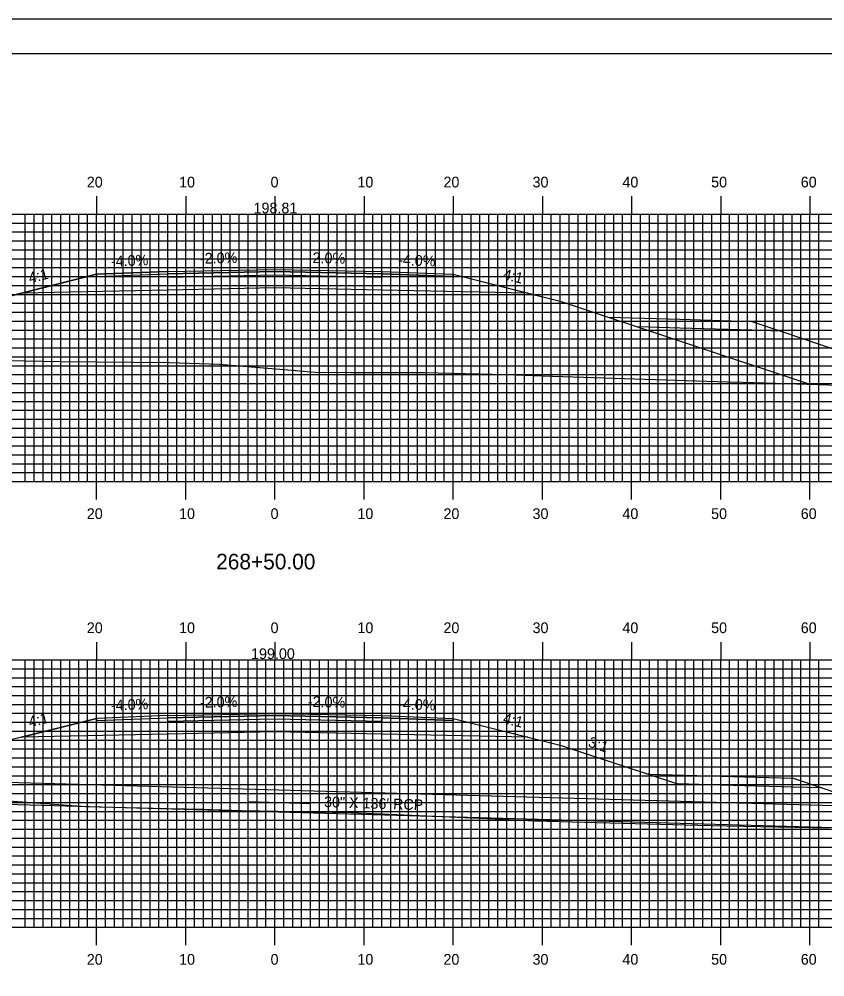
# Model space of a CAD drawing. Extents: x 1807832 to 1808175, y 442591 to 442811.
# Drawn here: x 1807969.1 to 1808059.5, y 442703.1 to 442810.5 of the extents above; entities that cross this region are included whole.
import ezdxf

# ---------------------------------------------------------------- set-up
doc = ezdxf.new("R2010")
doc.units = 0
for name, color, linetype in [('ANNOTATION', 7, 'Continuous'), ('BORDER', 7, 'Continuous'), ('D_Drainage_Culvert', 7, 'Continuous'), ('D_Drainage_Text', 7, 'Continuous'), ('D_Roadway_Centerline', 7, 'Continuous'), ('D_Roadway_Centerline_Text', 7, 'Continuous'), ('D_Roadway_Drive_Gravel', 7, 'Continuous'), ('D_Roadway_Edge_Shoulder', 7, 'Continuous'), ('D_Roadway_Edge_TW', 7, 'Continuous'), ('D_Roadway_FinishedGrade', 7, 'Continuous'), ('D_Roadway_Pavement', 7, 'Continuous'), ('D_Roadway_SlopeLines', 7, 'Continuous'), ('D_Roadway_SubGrade', 7, 'Continuous'), ('H_V ANNOTATION', 7, 'Continuous'), ('MAJOR', 7, 'Continuous'), ('MINOR', 7, 'Continuous'), ('PLOT BOUNDARY', 7, 'Continuous'), ('S_Roadway_Centerline', 7, 'Continuous')]:
    doc.layers.add(name, color=color, linetype=linetype)

msp = doc.modelspace()

# ---------------------------------------------------------------- linework, layer by layer
at = {"layer": 'BORDER'}
msp.add_lwpolyline([(1807848.18, 442596.67), (1808168.18, 442596.67), (1808168.18, 442806.67), (1807848.18, 442806.67)], close=True, dxfattribs=at)
at = {"layer": 'D_Drainage_Culvert'}
for p, q in [((1808039.7, 442725.85), (1808039.65, 442725.85)), ((1808042.97, 442724.76), (1808042.95, 442724.76)), ((1807994.78, 442722.79), (1808001.78, 442722.56))]:
    msp.add_line(p, q, dxfattribs=at)
msp.add_lwpolyline([(1807935.84, 442723.35), (1807935.9, 442725.84), (1808072.45, 442721.98), (1808072.39, 442719.49)], close=True, dxfattribs=at)
at = {"layer": 'D_Roadway_Centerline'}
msp.add_lwpolyline([(1807947.22, 442772.73), (1807965.78, 442778.92), (1807969.42, 442779.82), (1807977.78, 442781.92), (1807985.78, 442782.24), (1807997.78, 442782.48), (1808009.78, 442782.24), (1808017.78, 442781.92), (1808026.15, 442779.82), (1808029.78, 442778.92), (1808057.78, 442769.58)], dxfattribs=at)
at = {"layer": 'D_Roadway_Drive_Gravel'}
for points in [[(1808035.19, 442777.11), (1808043.19, 442776.88), (1808051.29, 442776.64), (1808054.53, 442775.55), (1808051.29, 442775.64), (1808043.19, 442775.88), (1808038.48, 442776.02)], [(1808039.7, 442725.84), (1808039.7, 442725.85), (1808047.8, 442725.62), (1808055.9, 442725.4), (1808059.14, 442724.31), (1808055.91, 442724.4), (1808047.81, 442724.62), (1808042.97, 442724.76)]]:
    msp.add_lwpolyline(points, dxfattribs=at)
at = {"layer": 'D_Roadway_Edge_Shoulder'}
for points in [[(1807985.78, 442782.24), (1807977.78, 442781.92), (1807977.78, 442781.67), (1807985.78, 442781.99)], [(1808009.78, 442782.24), (1808017.78, 442781.92), (1808017.78, 442781.67), (1808009.78, 442781.99)], [(1807985.78, 442732.42), (1807977.78, 442732.1), (1807977.78, 442731.85), (1807985.78, 442732.17)], [(1808009.78, 442732.42), (1808017.78, 442732.1), (1808017.78, 442731.85), (1808009.78, 442732.17)]]:
    msp.add_lwpolyline(points, close=True, dxfattribs=at)
at = {"layer": 'D_Roadway_Edge_TW'}
for points in [[(1807985.78, 442781.99), (1807985.78, 442782.24), (1807997.78, 442782.48), (1808009.78, 442782.24), (1808009.78, 442781.99), (1807997.78, 442782.23)], [(1807985.78, 442732.17), (1807985.78, 442732.42), (1807997.78, 442732.66), (1808009.78, 442732.42), (1808009.78, 442732.17), (1807997.78, 442732.41)]]:
    msp.add_lwpolyline(points, close=True, dxfattribs=at)
at = {"layer": 'D_Roadway_FinishedGrade'}
for p, q in [((1807977.78, 442732.1), (1807965.78, 442729.1)), ((1808054.15, 442719.94), (1808056.15, 442719.94))]:
    msp.add_line(p, q, dxfattribs=at)
at = {"layer": 'D_Roadway_Pavement'}
for points in [[(1807985.78, 442781.57), (1807985.78, 442781.99), (1807997.78, 442782.23), (1808009.78, 442781.99), (1808009.78, 442781.57), (1807997.78, 442781.81)], [(1807985.78, 442731.76), (1807985.78, 442732.17), (1807997.78, 442732.41), (1808009.78, 442732.17), (1808009.78, 442731.76), (1807997.78, 442732)]]:
    msp.add_lwpolyline(points, close=True, dxfattribs=at)
at = {"layer": 'D_Roadway_SlopeLines'}
for points in [[(1807977.78, 442781.92), (1807965.78, 442778.92), (1807947.22, 442772.73)], [(1808017.78, 442781.92), (1808029.78, 442778.92), (1808057.78, 442769.58)], [(1808051.29, 442776.64), (1808054.53, 442775.55), (1808073.28, 442769.2)], [(1808017.78, 442732.1), (1808029.78, 442729.1), (1808042.95, 442724.76)], [(1808055.9, 442725.4), (1808059.14, 442724.31), (1808062.76, 442723.09)]]:
    msp.add_lwpolyline(points, dxfattribs=at)
at = {"layer": 'D_Roadway_SubGrade'}
for points in [[(1807985.78, 442780.15), (1807969.42, 442779.82), (1807977.78, 442781.92), (1807977.78, 442781.67), (1807985.78, 442781.99), (1807997.78, 442782.23), (1808009.78, 442781.99), (1808017.78, 442781.67), (1808017.78, 442781.92), (1808026.15, 442779.82), (1808009.78, 442780.15), (1807997.78, 442780.39)], [(1807985.78, 442730.34), (1807969.42, 442730.01), (1807977.78, 442732.1), (1807977.78, 442731.85), (1807985.78, 442732.17), (1807997.78, 442732.41), (1808009.78, 442732.17), (1808017.78, 442731.85), (1808017.78, 442732.1), (1808026.15, 442730.01), (1808009.78, 442730.34), (1807997.78, 442730.58)]]:
    msp.add_lwpolyline(points, close=True, dxfattribs=at)
at = {"layer": 'MAJOR'}
for p, q in [((1807977.78, 442790.67), (1807977.78, 442788.67)), ((1807987.78, 442790.67), (1807987.78, 442788.67)), ((1807997.78, 442790.67), (1807997.78, 442788.67)), ((1808007.78, 442790.67), (1808007.78, 442788.67)), ((1808017.78, 442790.67), (1808017.78, 442788.67)), ((1808027.78, 442790.67), (1808027.78, 442788.67)), ((1808037.78, 442790.67), (1808037.78, 442788.67)), ((1808047.78, 442790.67), (1808047.78, 442788.67)), ((1808057.78, 442790.67), (1808057.78, 442788.67)), ((1807857.78, 442788.67), (1808137.78, 442788.67)), ((1807857.78, 442788.67), (1808137.78, 442788.67)), ((1807977.78, 442758.67), (1807977.78, 442788.67)), ((1807987.78, 442758.67), (1807987.78, 442788.67)), ((1807997.78, 442758.67), (1807997.78, 442788.67)), ((1808007.78, 442758.67), (1808007.78, 442788.67)), ((1808017.78, 442758.67), (1808017.78, 442788.67)), ((1808027.78, 442758.67), (1808027.78, 442788.67)), ((1808037.78, 442758.67), (1808037.78, 442788.67)), ((1808047.78, 442758.67), (1808047.78, 442788.67)), ((1808057.78, 442758.67), (1808057.78, 442788.67)), ((1807857.78, 442783.67), (1808137.78, 442783.67)), ((1807857.78, 442778.67), (1808137.78, 442778.67)), ((1807857.78, 442773.67), (1808137.78, 442773.67)), ((1807857.78, 442768.67), (1808137.78, 442768.67)), ((1807857.78, 442763.67), (1808137.78, 442763.67)), ((1807857.78, 442758.67), (1808137.78, 442758.67)), ((1807857.78, 442758.67), (1808137.78, 442758.67)), ((1807977.78, 442756.66), (1807977.78, 442758.67)), ((1807987.78, 442756.66), (1807987.78, 442758.67)), ((1807997.78, 442756.66), (1807997.78, 442758.67)), ((1808007.78, 442756.66), (1808007.78, 442758.67)), ((1808017.78, 442756.66), (1808017.78, 442758.67)), ((1808027.78, 442756.66), (1808027.78, 442758.67)), ((1808037.78, 442756.66), (1808037.78, 442758.67)), ((1808047.78, 442756.66), (1808047.78, 442758.67)), ((1808057.78, 442756.66), (1808057.78, 442758.67)), ((1807977.78, 442740.67), (1807977.78, 442738.67)), ((1807987.78, 442740.67), (1807987.78, 442738.67)), ((1807997.78, 442740.67), (1807997.78, 442738.67)), ((1808007.78, 442740.67), (1808007.78, 442738.67)), ((1808017.78, 442740.67), (1808017.78, 442738.67)), ((1808027.78, 442740.67), (1808027.78, 442738.67)), ((1808037.78, 442740.67), (1808037.78, 442738.67)), ((1808047.78, 442740.67), (1808047.78, 442738.67)), ((1808057.78, 442740.67), (1808057.78, 442738.67)), ((1807857.78, 442738.67), (1808137.78, 442738.67)), ((1807857.78, 442738.67), (1808137.78, 442738.67)), ((1807977.78, 442708.67), (1807977.78, 442738.67)), ((1807987.78, 442708.67), (1807987.78, 442738.67)), ((1807997.78, 442708.67), (1807997.78, 442738.67)), ((1808007.78, 442708.67), (1808007.78, 442738.67)), ((1808017.78, 442708.67), (1808017.78, 442738.67)), ((1808027.78, 442708.67), (1808027.78, 442738.67)), ((1808037.78, 442708.67), (1808037.78, 442738.67)), ((1808047.78, 442708.67), (1808047.78, 442738.67)), ((1808057.78, 442708.67), (1808057.78, 442738.67)), ((1807857.78, 442733.67), (1808137.78, 442733.67)), ((1807857.78, 442728.67), (1808137.78, 442728.67)), ((1807857.78, 442723.67), (1808137.78, 442723.67)), ((1807857.78, 442718.67), (1808137.78, 442718.67)), ((1807857.78, 442713.67), (1808137.78, 442713.67)), ((1807857.78, 442708.67), (1808137.78, 442708.67)), ((1807857.78, 442708.67), (1808137.78, 442708.67)), ((1807977.78, 442706.66), (1807977.78, 442708.67)), ((1807987.78, 442706.66), (1807987.78, 442708.67)), ((1807997.78, 442706.66), (1807997.78, 442708.67)), ((1808007.78, 442706.66), (1808007.78, 442708.67)), ((1808017.78, 442706.66), (1808017.78, 442708.67)), ((1808027.78, 442706.66), (1808027.78, 442708.67)), ((1808037.78, 442706.66), (1808037.78, 442708.67)), ((1808047.78, 442706.66), (1808047.78, 442708.67)), ((1808057.78, 442706.66), (1808057.78, 442708.67))]:
    msp.add_line(p, q, dxfattribs=at)
at = {"layer": 'MINOR'}
for p, q in [((1807969.78, 442758.67), (1807969.78, 442788.67)), ((1807970.78, 442758.67), (1807970.78, 442788.67)), ((1807971.78, 442758.67), (1807971.78, 442788.67)), ((1807972.78, 442758.67), (1807972.78, 442788.67)), ((1807973.78, 442758.67), (1807973.78, 442788.67)), ((1807974.78, 442758.67), (1807974.78, 442788.67)), ((1807975.78, 442758.67), (1807975.78, 442788.67)), ((1807976.78, 442758.67), (1807976.78, 442788.67)), ((1807978.78, 442758.67), (1807978.78, 442788.67)), ((1807979.78, 442758.67), (1807979.78, 442788.67)), ((1807980.78, 442758.67), (1807980.78, 442788.67)), ((1807981.78, 442758.67), (1807981.78, 442788.67)), ((1807982.78, 442758.67), (1807982.78, 442788.67)), ((1807983.78, 442758.67), (1807983.78, 442788.67)), ((1807984.78, 442758.67), (1807984.78, 442788.67)), ((1807985.78, 442758.67), (1807985.78, 442788.67)), ((1807986.78, 442758.67), (1807986.78, 442788.67)), ((1807988.78, 442758.67), (1807988.78, 442788.67)), ((1807989.78, 442758.67), (1807989.78, 442788.67)), ((1807990.78, 442758.67), (1807990.78, 442788.67)), ((1807991.78, 442758.67), (1807991.78, 442788.67)), ((1807992.78, 442758.67), (1807992.78, 442788.67)), ((1807993.78, 442758.67), (1807993.78, 442788.67)), ((1807994.78, 442758.67), (1807994.78, 442788.67)), ((1807995.78, 442758.67), (1807995.78, 442788.67)), ((1807996.78, 442758.67), (1807996.78, 442788.67)), ((1807998.78, 442758.67), (1807998.78, 442788.67)), ((1807999.78, 442758.67), (1807999.78, 442788.67)), ((1808000.78, 442758.67), (1808000.78, 442788.67)), ((1808001.78, 442758.67), (1808001.78, 442788.67)), ((1808002.78, 442758.67), (1808002.78, 442788.67)), ((1808003.78, 442758.67), (1808003.78, 442788.67)), ((1808004.78, 442758.67), (1808004.78, 442788.67)), ((1808005.78, 442758.67), (1808005.78, 442788.67)), ((1808006.78, 442758.67), (1808006.78, 442788.67)), ((1808008.78, 442758.67), (1808008.78, 442788.67)), ((1808009.78, 442758.67), (1808009.78, 442788.67)), ((1808010.78, 442758.67), (1808010.78, 442788.67)), ((1808011.78, 442758.67), (1808011.78, 442788.67)), ((1808012.78, 442758.67), (1808012.78, 442788.67)), ((1808013.78, 442758.67), (1808013.78, 442788.67)), ((1808014.78, 442758.67), (1808014.78, 442788.67)), ((1808015.78, 442758.67), (1808015.78, 442788.67)), ((1808016.78, 442758.67), (1808016.78, 442788.67)), ((1808018.78, 442758.67), (1808018.78, 442788.67)), ((1808019.78, 442758.67), (1808019.78, 442788.67)), ((1808020.78, 442758.67), (1808020.78, 442788.67)), ((1808021.78, 442758.67), (1808021.78, 442788.67)), ((1808022.78, 442758.67), (1808022.78, 442788.67)), ((1808023.78, 442758.67), (1808023.78, 442788.67)), ((1808024.78, 442758.67), (1808024.78, 442788.67)), ((1808025.78, 442758.67), (1808025.78, 442788.67)), ((1808026.78, 442758.67), (1808026.78, 442788.67)), ((1808028.78, 442758.67), (1808028.78, 442788.67)), ((1808029.78, 442758.67), (1808029.78, 442788.67)), ((1808030.78, 442758.67), (1808030.78, 442788.67)), ((1808031.78, 442758.67), (1808031.78, 442788.67)), ((1808032.78, 442758.67), (1808032.78, 442788.67)), ((1808033.78, 442758.67), (1808033.78, 442788.67)), ((1808034.78, 442758.67), (1808034.78, 442788.67)), ((1808035.78, 442758.67), (1808035.78, 442788.67)), ((1808036.78, 442758.67), (1808036.78, 442788.67)), ((1808038.78, 442758.67), (1808038.78, 442788.67)), ((1808039.78, 442758.67), (1808039.78, 442788.67)), ((1808040.78, 442758.67), (1808040.78, 442788.67)), ((1808041.78, 442758.67), (1808041.78, 442788.67)), ((1808042.78, 442758.67), (1808042.78, 442788.67)), ((1808043.78, 442758.67), (1808043.78, 442788.67)), ((1808044.78, 442758.67), (1808044.78, 442788.67)), ((1808045.78, 442758.67), (1808045.78, 442788.67)), ((1808046.78, 442758.67), (1808046.78, 442788.67)), ((1808048.78, 442758.67), (1808048.78, 442788.67)), ((1808049.78, 442758.67), (1808049.78, 442788.67)), ((1808050.78, 442758.67), (1808050.78, 442788.67)), ((1808051.78, 442758.67), (1808051.78, 442788.67)), ((1808052.78, 442758.67), (1808052.78, 442788.67)), ((1808053.78, 442758.67), (1808053.78, 442788.67)), ((1808054.78, 442758.67), (1808054.78, 442788.67)), ((1808055.78, 442758.67), (1808055.78, 442788.67)), ((1808056.78, 442758.67), (1808056.78, 442788.67)), ((1808058.78, 442758.67), (1808058.78, 442788.67)), ((1807857.78, 442787.67), (1808137.78, 442787.67)), ((1807857.78, 442786.67), (1808137.78, 442786.67)), ((1807857.78, 442785.67), (1808137.78, 442785.67)), ((1807857.78, 442784.67), (1808137.78, 442784.67)), ((1807857.78, 442782.67), (1808137.78, 442782.67)), ((1807857.78, 442781.67), (1808137.78, 442781.67)), ((1807857.78, 442780.67), (1808137.78, 442780.67)), ((1807857.78, 442779.67), (1808137.78, 442779.67)), ((1807857.78, 442777.67), (1808137.78, 442777.67)), ((1807857.78, 442776.67), (1808137.78, 442776.67)), ((1807857.78, 442775.67), (1808137.78, 442775.67)), ((1807857.78, 442774.67), (1808137.78, 442774.67)), ((1807857.78, 442772.67), (1808137.78, 442772.67)), ((1807857.78, 442771.67), (1808137.78, 442771.67)), ((1807857.78, 442770.67), (1808137.78, 442770.67)), ((1807857.78, 442769.67), (1808137.78, 442769.67)), ((1807857.78, 442767.67), (1808137.78, 442767.67)), ((1807857.78, 442766.67), (1808137.78, 442766.67)), ((1807857.78, 442765.67), (1808137.78, 442765.67)), ((1807857.78, 442764.67), (1808137.78, 442764.67)), ((1807857.78, 442762.67), (1808137.78, 442762.67)), ((1807857.78, 442761.67), (1808137.78, 442761.67)), ((1807857.78, 442760.67), (1808137.78, 442760.67)), ((1807857.78, 442759.67), (1808137.78, 442759.67)), ((1807969.78, 442708.67), (1807969.78, 442738.67)), ((1807970.78, 442708.67), (1807970.78, 442738.67)), ((1807971.78, 442708.67), (1807971.78, 442738.67)), ((1807972.78, 442708.67), (1807972.78, 442738.67)), ((1807973.78, 442708.67), (1807973.78, 442738.67)), ((1807974.78, 442708.67), (1807974.78, 442738.67)), ((1807975.78, 442708.67), (1807975.78, 442738.67)), ((1807976.78, 442708.67), (1807976.78, 442738.67)), ((1807978.78, 442708.67), (1807978.78, 442738.67)), ((1807979.78, 442708.67), (1807979.78, 442738.67)), ((1807980.78, 442708.67), (1807980.78, 442738.67)), ((1807981.78, 442708.67), (1807981.78, 442738.67)), ((1807982.78, 442708.67), (1807982.78, 442738.67)), ((1807983.78, 442708.67), (1807983.78, 442738.67)), ((1807984.78, 442708.67), (1807984.78, 442738.67)), ((1807985.78, 442708.67), (1807985.78, 442738.67)), ((1807986.78, 442708.67), (1807986.78, 442738.67)), ((1807988.78, 442708.67), (1807988.78, 442738.67)), ((1807989.78, 442708.67), (1807989.78, 442738.67)), ((1807990.78, 442708.67), (1807990.78, 442738.67)), ((1807991.78, 442708.67), (1807991.78, 442738.67)), ((1807992.78, 442708.67), (1807992.78, 442738.67)), ((1807993.78, 442708.67), (1807993.78, 442738.67)), ((1807994.78, 442708.67), (1807994.78, 442738.67)), ((1807995.78, 442708.67), (1807995.78, 442738.67)), ((1807996.78, 442708.67), (1807996.78, 442738.67)), ((1807998.78, 442708.67), (1807998.78, 442738.67)), ((1807999.78, 442708.67), (1807999.78, 442738.67)), ((1808000.78, 442708.67), (1808000.78, 442738.67)), ((1808001.78, 442708.67), (1808001.78, 442738.67)), ((1808002.78, 442708.67), (1808002.78, 442738.67)), ((1808003.78, 442708.67), (1808003.78, 442738.67)), ((1808004.78, 442708.67), (1808004.78, 442738.67)), ((1808005.78, 442708.67), (1808005.78, 442738.67)), ((1808006.78, 442708.67), (1808006.78, 442738.67)), ((1808008.78, 442708.67), (1808008.78, 442738.67)), ((1808009.78, 442708.67), (1808009.78, 442738.67)), ((1808010.78, 442708.67), (1808010.78, 442738.67)), ((1808011.78, 442708.67), (1808011.78, 442738.67)), ((1808012.78, 442708.67), (1808012.78, 442738.67)), ((1808013.78, 442708.67), (1808013.78, 442738.67)), ((1808014.78, 442708.67), (1808014.78, 442738.67)), ((1808015.78, 442708.67), (1808015.78, 442738.67)), ((1808016.78, 442708.67), (1808016.78, 442738.67)), ((1808018.78, 442708.67), (1808018.78, 442738.67)), ((1808019.78, 442708.67), (1808019.78, 442738.67)), ((1808020.78, 442708.67), (1808020.78, 442738.67)), ((1808021.78, 442708.67), (1808021.78, 442738.67)), ((1808022.78, 442708.67), (1808022.78, 442738.67)), ((1808023.78, 442708.67), (1808023.78, 442738.67)), ((1808024.78, 442708.67), (1808024.78, 442738.67)), ((1808025.78, 442708.67), (1808025.78, 442738.67)), ((1808026.78, 442708.67), (1808026.78, 442738.67)), ((1808028.78, 442708.67), (1808028.78, 442738.67)), ((1808029.78, 442708.67), (1808029.78, 442738.67)), ((1808030.78, 442708.67), (1808030.78, 442738.67)), ((1808031.78, 442708.67), (1808031.78, 442738.67)), ((1808032.78, 442708.67), (1808032.78, 442738.67)), ((1808033.78, 442708.67), (1808033.78, 442738.67)), ((1808034.78, 442708.67), (1808034.78, 442738.67)), ((1808035.78, 442708.67), (1808035.78, 442738.67)), ((1808036.78, 442708.67), (1808036.78, 442738.67)), ((1808038.78, 442708.67), (1808038.78, 442738.67)), ((1808039.78, 442708.67), (1808039.78, 442738.67)), ((1808040.78, 442708.67), (1808040.78, 442738.67)), ((1808041.78, 442708.67), (1808041.78, 442738.67)), ((1808042.78, 442708.67), (1808042.78, 442738.67)), ((1808043.78, 442708.67), (1808043.78, 442738.67)), ((1808044.78, 442708.67), (1808044.78, 442738.67)), ((1808045.78, 442708.67), (1808045.78, 442738.67)), ((1808046.78, 442708.67), (1808046.78, 442738.67)), ((1808048.78, 442708.67), (1808048.78, 442738.67)), ((1808049.78, 442708.67), (1808049.78, 442738.67)), ((1808050.78, 442708.67), (1808050.78, 442738.67)), ((1808051.78, 442708.67), (1808051.78, 442738.67)), ((1808052.78, 442708.67), (1808052.78, 442738.67)), ((1808053.78, 442708.67), (1808053.78, 442738.67)), ((1808054.78, 442708.67), (1808054.78, 442738.67)), ((1808055.78, 442708.67), (1808055.78, 442738.67)), ((1808056.78, 442708.67), (1808056.78, 442738.67)), ((1808058.78, 442708.67), (1808058.78, 442738.67)), ((1807857.78, 442737.67), (1808137.78, 442737.67)), ((1807857.78, 442736.67), (1808137.78, 442736.67)), ((1807857.78, 442735.67), (1808137.78, 442735.67)), ((1807857.78, 442734.67), (1808137.78, 442734.67)), ((1807857.78, 442732.67), (1808137.78, 442732.67)), ((1807857.78, 442731.67), (1808137.78, 442731.67)), ((1807857.78, 442730.67), (1808137.78, 442730.67)), ((1807857.78, 442729.67), (1808137.78, 442729.67)), ((1807857.78, 442727.67), (1808137.78, 442727.67)), ((1807857.78, 442726.67), (1808137.78, 442726.67)), ((1807857.78, 442725.67), (1808137.78, 442725.67)), ((1807857.78, 442724.67), (1808137.78, 442724.67)), ((1807857.78, 442722.67), (1808137.78, 442722.67)), ((1807857.78, 442721.67), (1808137.78, 442721.67)), ((1807857.78, 442720.67), (1808137.78, 442720.67)), ((1807857.78, 442719.67), (1808137.78, 442719.67)), ((1807857.78, 442717.67), (1808137.78, 442717.67)), ((1807857.78, 442716.67), (1808137.78, 442716.67)), ((1807857.78, 442715.67), (1808137.78, 442715.67)), ((1807857.78, 442714.67), (1808137.78, 442714.67)), ((1807857.78, 442712.67), (1808137.78, 442712.67)), ((1807857.78, 442711.67), (1808137.78, 442711.67)), ((1807857.78, 442710.67), (1808137.78, 442710.67)), ((1807857.78, 442709.67), (1808137.78, 442709.67))]:
    msp.add_line(p, q, dxfattribs=at)
at = {"layer": 'PLOT BOUNDARY'}
msp.add_lwpolyline([(1807832, 442590.55), (1808172, 442590.55), (1808172, 442810.55), (1807832, 442810.55)], close=True, dxfattribs=at)
at = {"layer": 'S_Roadway_Centerline'}
for points in [[(1807921.73, 442772.99), (1807936.94, 442772.83), (1807943.07, 442772.78), (1807944, 442772.75), (1807955.13, 442772.68), (1807963.52, 442772.31), (1807973.83, 442772.15), (1807985.96, 442772.04), (1807991.54, 442771.85), (1807998.32, 442771.27), (1808002.31, 442770.94), (1808006.3, 442770.89), (1808014.57, 442770.89), (1808023.69, 442770.68), (1808027.77, 442770.53), (1808048.54, 442769.86), (1808050.25, 442769.82), (1808061.12, 442769.48)], [(1807920.41, 442723.96), (1807940.51, 442723.16), (1807941.87, 442723.15), (1807951.89, 442723.25), (1807964.47, 442722.97), (1807968.44, 442722.8), (1807976.59, 442722.22), (1807985.68, 442721.99), (1807989.66, 442721.9), (1807994.01, 442721.76), (1808006.29, 442721.55), (1808023.34, 442720.81), (1808026.89, 442720.61), (1808045.21, 442720.11), (1808048.45, 442720.04), (1808059.94, 442719.83)]]:
    msp.add_lwpolyline(points, dxfattribs=at)

# ---------------------------------------------------------------- texts
at = {"layer": 'ANNOTATION'}
for s, rotation, p in [('-4.0%', 2.2906, (1807979.42, 442782.78)), ('-2.0%', 1.1458, (1807989.39, 442783.11)), ('-2.0%', 358.8542, (1808001.47, 442783.2)), ('-4.0%', 357.7094, (1808011.58, 442782.97)), ('4:1', 14.0362, (1807970.32, 442780.91)), ('4:1', 345.9638, (1808023.29, 442781.4)), ('-4.0%', 2.2906, (1807979.42, 442732.97)), ('-2.0%', 1.1458, (1807989.39, 442733.3)), ('-2.0%', 358.8542, (1808001.47, 442733.39)), ('-4.0%', 357.7094, (1808011.58, 442733.15)), ('4:1', 14.0362, (1807970.32, 442731.1)), ('4:1', 345.9638, (1808023.29, 442731.59)), ('3:1', 341.5652, (1808032.84, 442728.96))]:
    msp.add_text(s, height=1.2, rotation=rotation, dxfattribs=at).set_placement(p)
at = {"layer": 'D_Drainage_Text'}
msp.add_text('30" X 136\' RCP', height=1.2, rotation=358.1149, dxfattribs=at).set_placement((1808003.28, 442722.16))
at = {"layer": 'D_Roadway_Centerline'}
for s, p in [('C', (1807997.78, 442782.48)), ('L', (1807997.78, 442782.47))]:
    msp.add_text(s, height=0.0146, dxfattribs=at).set_placement(p)
at = {"layer": 'D_Roadway_Centerline_Text'}
for s, p in [('198.81', (1807995.39, 442788.76)), ('199.00', (1807995.11, 442738.76))]:
    msp.add_text(s, height=1.2, dxfattribs=at).set_placement(p)
at = {"layer": 'H_V ANNOTATION'}
for s, height, p in [('20', 1.2, (1807976.69, 442791.67)), ('10', 1.2, (1807987.04, 442791.67)), ('0', 1.2, (1807997.3, 442791.67)), ('10', 1.2, (1808007.04, 442791.67)), ('20', 1.2, (1808016.69, 442791.67)), ('30', 1.2, (1808026.68, 442791.67)), ('40', 1.2, (1808036.76, 442791.67)), ('50', 1.2, (1808046.71, 442791.67)), ('60', 1.2, (1808056.76, 442791.67)), ('20', 1.2, (1807976.69, 442754.47)), ('10', 1.2, (1807987.04, 442754.47)), ('0', 1.2, (1807997.3, 442754.47)), ('10', 1.2, (1808007.04, 442754.47)), ('20', 1.2, (1808016.69, 442754.47)), ('30', 1.2, (1808026.68, 442754.47)), ('40', 1.2, (1808036.76, 442754.47)), ('50', 1.2, (1808046.71, 442754.47)), ('60', 1.2, (1808056.76, 442754.47)), ('268+50.00', 1.75, (1807991.2, 442748.82)), ('20', 1.2, (1807976.69, 442741.67)), ('10', 1.2, (1807987.04, 442741.67)), ('0', 1.2, (1807997.3, 442741.67)), ('10', 1.2, (1808007.04, 442741.67)), ('20', 1.2, (1808016.69, 442741.67)), ('30', 1.2, (1808026.68, 442741.67)), ('40', 1.2, (1808036.76, 442741.67)), ('50', 1.2, (1808046.71, 442741.67)), ('60', 1.2, (1808056.76, 442741.67)), ('20', 1.2, (1807976.69, 442704.47)), ('10', 1.2, (1807987.04, 442704.47)), ('0', 1.2, (1807997.3, 442704.47)), ('10', 1.2, (1808007.04, 442704.47)), ('20', 1.2, (1808016.69, 442704.47)), ('30', 1.2, (1808026.68, 442704.47)), ('40', 1.2, (1808036.76, 442704.47)), ('50', 1.2, (1808046.71, 442704.47)), ('60', 1.2, (1808056.76, 442704.47))]:
    msp.add_text(s, height=height, dxfattribs=at).set_placement(p)

doc.saveas('drawing.dxf')
